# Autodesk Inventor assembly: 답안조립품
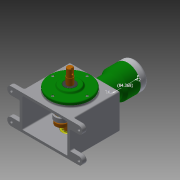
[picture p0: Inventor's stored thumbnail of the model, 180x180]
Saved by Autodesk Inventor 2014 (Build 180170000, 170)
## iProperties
Created: 2016-11
Part Number: 답안조립품
Document SubType Name: Assembly
Designer: NET
Author: NET
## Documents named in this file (16)
- C:\Users\NET\Desktop\361107V1007\답안조립품.iam
- C:\Users\NET\Desktop\361107V1007\본체.ipt
- C:\Users\NET\Desktop\361107V1007\가변스프링.ipt
- C:\Users\NET\Desktop\361107V1007\메인크랭크축.ipt
- C:\Users\NET\Desktop\361107V1007\베어링 20 x 47 x 14.ipt
- C:\Users\NET\Desktop\361107V1007\베어링 NA 4902.ipt
- C:\Users\NET\Desktop\361107V1007\볼트 M4 x 8.ipt
- C:\Users\NET\Desktop\361107V1007\볼트 M5 x 20.ipt
- C:\Users\NET\Desktop\361107V1007\실린더.ipt
- C:\Users\NET\Desktop\361107V1007\실린더헤드.ipt
- C:\Users\NET\Desktop\361107V1007\앞커버.ipt
- C:\Users\NET\Desktop\361107V1007\오일 실 20 35 8.ipt
- C:\Users\NET\Desktop\361107V1007\커넥팅로드.ipt
- C:\Users\NET\Desktop\361107V1007\크랭크보조축.ipt
- C:\Users\NET\Desktop\361107V1007\피스톤.ipt
- C:\Users\NET\Desktop\361107V1007\피스톤핀.ipt
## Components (15 placed, 5 different names)
1. 피스톤:1
2. 피스톤핀:1
3. 가변스프링:1
4. ISO 4762 M4 x 8:1
5. ISO 4762 M4 x 8:2
6. ISO 4762 M4 x 8:3
7. ISO 4762 M4 x 8:4
8. ISO 4762 M4 x 8:5
9. ISO 4762 M4 x 8:6
10. ISO 4762 M4 x 8:7
11. ISO 4762 M4 x 8:8
12. ISO 4762 M5 x 20:1
13. ISO 4762 M5 x 20:2
14. ISO 4762 M5 x 20:3
15. ISO 4762 M5 x 20:4
